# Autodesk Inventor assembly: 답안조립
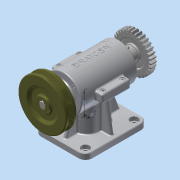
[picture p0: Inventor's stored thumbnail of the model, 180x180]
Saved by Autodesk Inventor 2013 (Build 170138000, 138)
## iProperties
Created: 2015-09
Part Number: 답안조립
Document SubType Name: Assembly
Designer: WINDOWS7
Mass: 2251.16 g
Surface Area: 1633.52 cm^2
Volume: 528.514 cm^3
Density: 4.25942 g/cm^3
Author: WINDOWS7
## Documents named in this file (17)
- C:\Users\WINDOWS7\Desktop\350908V1010\답안조립.iam
- C:\Users\WINDOWS7\Desktop\350908V1010\본체.ipt
- C:\Users\WINDOWS7\Desktop\350908V1010\M3x0.5x8.ipt
- C:\Users\WINDOWS7\Desktop\350908V1010\M4x0.5x14.ipt
- C:\Users\WINDOWS7\Desktop\350908V1010\V-벨트풀리.ipt
- C:\Users\WINDOWS7\Desktop\350908V1010\뒤커버.ipt
- C:\Users\WINDOWS7\Desktop\350908V1010\멈춤나사.ipt
- C:\Users\WINDOWS7\Desktop\350908V1010\베어링 6201.ipt
- C:\Users\WINDOWS7\Desktop\350908V1010\베어링 6202.ipt
- C:\Users\WINDOWS7\Desktop\350908V1010\본체 커버.ipt
- C:\Users\WINDOWS7\Desktop\350908V1010\스퍼기어.ipt
- C:\Users\WINDOWS7\Desktop\350908V1010\스프링 - [가변].ipt
- C:\Users\WINDOWS7\Desktop\350908V1010\슬라이드.ipt
- C:\Users\WINDOWS7\Desktop\350908V1010\앞커버.ipt
- C:\Users\WINDOWS7\Desktop\350908V1010\오일실.ipt
- C:\Users\WINDOWS7\Desktop\350908V1010\키4x4.ipt
- C:\Users\WINDOWS7\Desktop\350908V1010\편심축.ipt
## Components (13 placed, 3 different names)
1. M4x0.5x14:1
2. V-벨트풀리:1
3. M4x0.5x14:2
4. M4x0.5x14:3
5. M4x0.5x14:4
6. M3x0.5x8:1
7. M3x0.5x8:2
8. M3x0.5x8:3
9. M3x0.5x8:4
10. M3x0.5x8:5
11. M3x0.5x8:6
12. M3x0.5x8:7
13. M3x0.5x8:8
